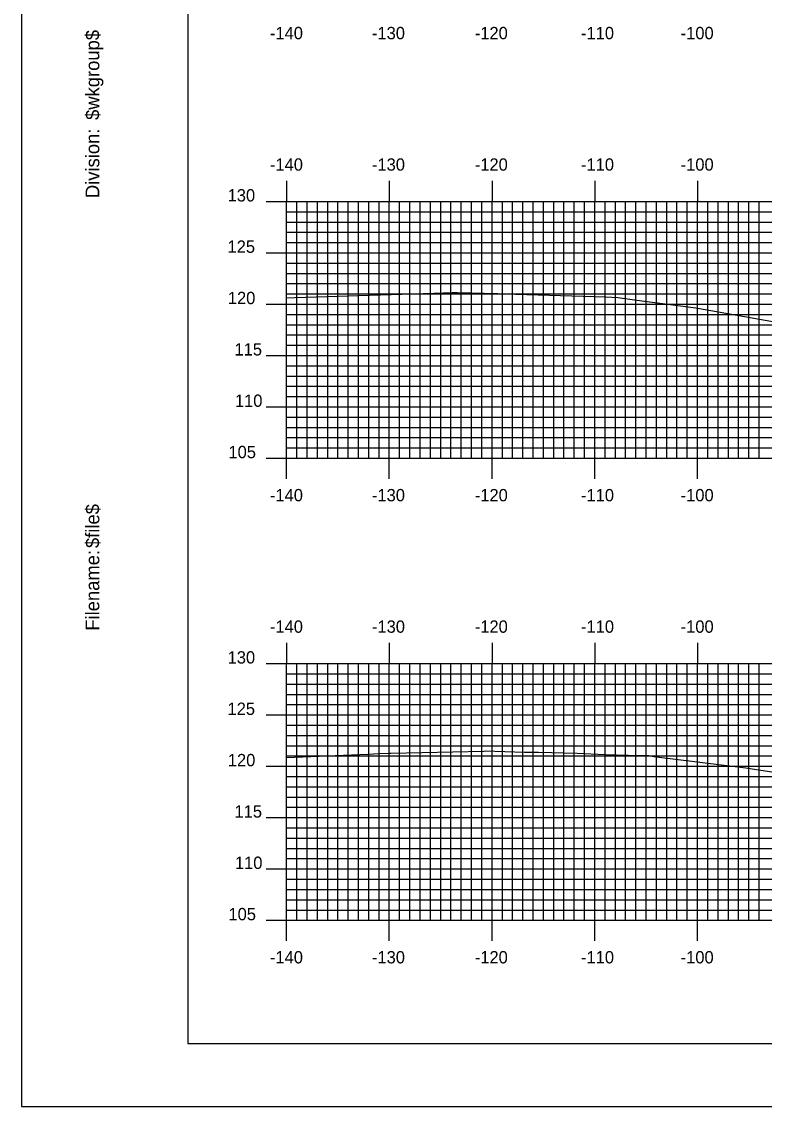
# Model space of a CAD drawing. Extents: x 844143 to 844486, y 363538 to 363758.
# Drawn here: x 844142.7 to 844215, y 363537.6 to 363643.2 of the extents above; entities that cross this region are included whole.
import ezdxf

# ---------------------------------------------------------------- set-up
doc = ezdxf.new("R2010")
doc.units = 0
for name, color, linetype in [('BORDER', 7, 'Continuous'), ('H_V ANNOTATION', 7, 'Continuous'), ('M_Roadway_Centerline', 7, 'Continuous'), ('MAJOR', 7, 'Continuous'), ('MINOR', 7, 'Continuous'), ('PLOT BOUNDARY', 7, 'Continuous'), ('S_Roadway_Centerline', 7, 'Continuous')]:
    doc.layers.add(name, color=color, linetype=linetype)

msp = doc.modelspace()

# ---------------------------------------------------------------- linework, layer by layer
at = {"layer": 'BORDER'}
msp.add_lwpolyline([(844158.85, 363543.72), (844478.85, 363543.72), (844478.85, 363753.72), (844158.85, 363753.72)], close=True, dxfattribs=at)
at = {"layer": 'MAJOR'}
for p, q in [((844168.45, 363627.73), (844168.45, 363625.72)), ((844178.45, 363627.73), (844178.45, 363625.72)), ((844188.45, 363627.73), (844188.45, 363625.72)), ((844198.45, 363627.73), (844198.45, 363625.72)), ((844208.45, 363627.73), (844208.45, 363625.72)), ((844166.45, 363625.72), (844168.45, 363625.72)), ((844168.45, 363625.72), (844448.45, 363625.72)), ((844168.45, 363600.72), (844168.45, 363625.72)), ((844168.45, 363600.72), (844168.45, 363625.72)), ((844168.45, 363625.72), (844448.45, 363625.72)), ((844178.45, 363600.72), (844178.45, 363625.72)), ((844188.45, 363600.72), (844188.45, 363625.72)), ((844198.45, 363600.72), (844198.45, 363625.72)), ((844208.45, 363600.72), (844208.45, 363625.72)), ((844166.45, 363620.72), (844168.45, 363620.72)), ((844168.45, 363620.72), (844448.45, 363620.72)), ((844166.45, 363615.72), (844168.45, 363615.72)), ((844168.45, 363615.72), (844448.45, 363615.72)), ((844166.45, 363610.72), (844168.45, 363610.72)), ((844168.45, 363610.72), (844448.45, 363610.72)), ((844166.45, 363605.72), (844168.45, 363605.72)), ((844168.45, 363605.72), (844448.45, 363605.72)), ((844166.45, 363600.72), (844168.45, 363600.72)), ((844168.45, 363600.72), (844448.45, 363600.72)), ((844168.45, 363600.72), (844448.45, 363600.72)), ((844168.45, 363598.72), (844168.45, 363600.72)), ((844178.45, 363598.72), (844178.45, 363600.72)), ((844188.45, 363598.72), (844188.45, 363600.72)), ((844198.45, 363598.72), (844198.45, 363600.72)), ((844208.45, 363598.72), (844208.45, 363600.72)), ((844168.45, 363582.73), (844168.45, 363580.72)), ((844178.45, 363582.73), (844178.45, 363580.72)), ((844188.45, 363582.73), (844188.45, 363580.72)), ((844198.45, 363582.73), (844198.45, 363580.72)), ((844208.45, 363582.73), (844208.45, 363580.72)), ((844166.45, 363580.72), (844168.45, 363580.72)), ((844168.45, 363580.72), (844448.45, 363580.72)), ((844168.45, 363555.72), (844168.45, 363580.72)), ((844168.45, 363555.72), (844168.45, 363580.72)), ((844168.45, 363580.72), (844448.45, 363580.72)), ((844178.45, 363555.72), (844178.45, 363580.72)), ((844188.45, 363555.72), (844188.45, 363580.72)), ((844198.45, 363555.72), (844198.45, 363580.72)), ((844208.45, 363555.72), (844208.45, 363580.72)), ((844166.45, 363575.72), (844168.45, 363575.72)), ((844168.45, 363575.72), (844448.45, 363575.72)), ((844166.45, 363570.72), (844168.45, 363570.72)), ((844168.45, 363570.72), (844448.45, 363570.72)), ((844166.45, 363565.72), (844168.45, 363565.72)), ((844168.45, 363565.72), (844448.45, 363565.72)), ((844166.45, 363560.72), (844168.45, 363560.72)), ((844168.45, 363560.72), (844448.45, 363560.72)), ((844166.45, 363555.72), (844168.45, 363555.72)), ((844168.45, 363555.72), (844448.45, 363555.72)), ((844168.45, 363555.72), (844448.45, 363555.72)), ((844168.45, 363553.72), (844168.45, 363555.72)), ((844178.45, 363553.72), (844178.45, 363555.72)), ((844188.45, 363553.72), (844188.45, 363555.72)), ((844198.45, 363553.72), (844198.45, 363555.72)), ((844208.45, 363553.72), (844208.45, 363555.72))]:
    msp.add_line(p, q, dxfattribs=at)
at = {"layer": 'MINOR'}
for p, q in [((844169.45, 363600.72), (844169.45, 363625.72)), ((844170.45, 363600.72), (844170.45, 363625.72)), ((844171.45, 363600.72), (844171.45, 363625.72)), ((844172.45, 363600.72), (844172.45, 363625.72)), ((844173.45, 363600.72), (844173.45, 363625.72)), ((844174.45, 363600.72), (844174.45, 363625.72)), ((844175.45, 363600.72), (844175.45, 363625.72)), ((844176.45, 363600.72), (844176.45, 363625.72)), ((844177.45, 363600.72), (844177.45, 363625.72)), ((844179.45, 363600.72), (844179.45, 363625.72)), ((844180.45, 363600.72), (844180.45, 363625.72)), ((844181.45, 363600.72), (844181.45, 363625.72)), ((844182.45, 363600.72), (844182.45, 363625.72)), ((844183.45, 363600.72), (844183.45, 363625.72)), ((844184.45, 363600.72), (844184.45, 363625.72)), ((844185.45, 363600.72), (844185.45, 363625.72)), ((844186.45, 363600.72), (844186.45, 363625.72)), ((844187.45, 363600.72), (844187.45, 363625.72)), ((844189.45, 363600.72), (844189.45, 363625.72)), ((844190.45, 363600.72), (844190.45, 363625.72)), ((844191.45, 363600.72), (844191.45, 363625.72)), ((844192.45, 363600.72), (844192.45, 363625.72)), ((844193.45, 363600.72), (844193.45, 363625.72)), ((844194.45, 363600.72), (844194.45, 363625.72)), ((844195.45, 363600.72), (844195.45, 363625.72)), ((844196.45, 363600.72), (844196.45, 363625.72)), ((844197.45, 363600.72), (844197.45, 363625.72)), ((844199.45, 363600.72), (844199.45, 363625.72)), ((844200.45, 363600.72), (844200.45, 363625.72)), ((844201.45, 363600.72), (844201.45, 363625.72)), ((844202.45, 363600.72), (844202.45, 363625.72)), ((844203.45, 363600.72), (844203.45, 363625.72)), ((844204.45, 363600.72), (844204.45, 363625.72)), ((844205.45, 363600.72), (844205.45, 363625.72)), ((844206.45, 363600.72), (844206.45, 363625.72)), ((844207.45, 363600.72), (844207.45, 363625.72)), ((844209.45, 363600.72), (844209.45, 363625.72)), ((844210.45, 363600.72), (844210.45, 363625.72)), ((844211.45, 363600.72), (844211.45, 363625.72)), ((844212.45, 363600.72), (844212.45, 363625.72)), ((844213.45, 363600.72), (844213.45, 363625.72)), ((844214.45, 363600.72), (844214.45, 363625.72)), ((844168.45, 363624.72), (844448.45, 363624.72)), ((844168.45, 363624.72), (844170.45, 363624.72)), ((844168.45, 363623.72), (844448.45, 363623.72)), ((844168.45, 363623.72), (844170.45, 363623.72)), ((844168.45, 363622.72), (844448.45, 363622.72)), ((844168.45, 363622.72), (844170.45, 363622.72)), ((844168.45, 363621.72), (844448.45, 363621.72)), ((844168.45, 363621.72), (844170.45, 363621.72)), ((844168.45, 363619.72), (844448.45, 363619.72)), ((844168.45, 363619.72), (844170.45, 363619.72)), ((844168.45, 363618.72), (844448.45, 363618.72)), ((844168.45, 363618.72), (844170.45, 363618.72)), ((844168.45, 363617.72), (844448.45, 363617.72)), ((844168.45, 363617.72), (844170.45, 363617.72)), ((844168.45, 363616.72), (844448.45, 363616.72)), ((844168.45, 363616.72), (844170.45, 363616.72)), ((844168.45, 363614.72), (844448.45, 363614.72)), ((844168.45, 363614.72), (844170.45, 363614.72)), ((844168.45, 363613.72), (844448.45, 363613.72)), ((844168.45, 363613.72), (844170.45, 363613.72)), ((844168.45, 363612.72), (844448.45, 363612.72)), ((844168.45, 363612.72), (844170.45, 363612.72)), ((844168.45, 363611.72), (844448.45, 363611.72)), ((844168.45, 363611.72), (844170.45, 363611.72)), ((844168.45, 363609.72), (844448.45, 363609.72)), ((844168.45, 363609.72), (844170.45, 363609.72)), ((844168.45, 363608.72), (844448.45, 363608.72)), ((844168.45, 363608.72), (844170.45, 363608.72)), ((844168.45, 363607.72), (844448.45, 363607.72)), ((844168.45, 363607.72), (844170.45, 363607.72)), ((844168.45, 363606.72), (844448.45, 363606.72)), ((844168.45, 363606.72), (844170.45, 363606.72)), ((844168.45, 363604.72), (844448.45, 363604.72)), ((844168.45, 363604.72), (844170.45, 363604.72)), ((844168.45, 363603.72), (844448.45, 363603.72)), ((844168.45, 363603.72), (844170.45, 363603.72)), ((844168.45, 363602.72), (844448.45, 363602.72)), ((844168.45, 363602.72), (844170.45, 363602.72)), ((844168.45, 363601.72), (844448.45, 363601.72)), ((844168.45, 363601.72), (844170.45, 363601.72)), ((844169.45, 363555.72), (844169.45, 363580.72)), ((844170.45, 363555.72), (844170.45, 363580.72)), ((844171.45, 363555.72), (844171.45, 363580.72)), ((844172.45, 363555.72), (844172.45, 363580.72)), ((844173.45, 363555.72), (844173.45, 363580.72)), ((844174.45, 363555.72), (844174.45, 363580.72)), ((844175.45, 363555.72), (844175.45, 363580.72)), ((844176.45, 363555.72), (844176.45, 363580.72)), ((844177.45, 363555.72), (844177.45, 363580.72)), ((844179.45, 363555.72), (844179.45, 363580.72)), ((844180.45, 363555.72), (844180.45, 363580.72)), ((844181.45, 363555.72), (844181.45, 363580.72)), ((844182.45, 363555.72), (844182.45, 363580.72)), ((844183.45, 363555.72), (844183.45, 363580.72)), ((844184.45, 363555.72), (844184.45, 363580.72)), ((844185.45, 363555.72), (844185.45, 363580.72)), ((844186.45, 363555.72), (844186.45, 363580.72)), ((844187.45, 363555.72), (844187.45, 363580.72)), ((844189.45, 363555.72), (844189.45, 363580.72)), ((844190.45, 363555.72), (844190.45, 363580.72)), ((844191.45, 363555.72), (844191.45, 363580.72)), ((844192.45, 363555.72), (844192.45, 363580.72)), ((844193.45, 363555.72), (844193.45, 363580.72)), ((844194.45, 363555.72), (844194.45, 363580.72)), ((844195.45, 363555.72), (844195.45, 363580.72)), ((844196.45, 363555.72), (844196.45, 363580.72)), ((844197.45, 363555.72), (844197.45, 363580.72)), ((844199.45, 363555.72), (844199.45, 363580.72)), ((844200.45, 363555.72), (844200.45, 363580.72)), ((844201.45, 363555.72), (844201.45, 363580.72)), ((844202.45, 363555.72), (844202.45, 363580.72)), ((844203.45, 363555.72), (844203.45, 363580.72)), ((844204.45, 363555.72), (844204.45, 363580.72)), ((844205.45, 363555.72), (844205.45, 363580.72)), ((844206.45, 363555.72), (844206.45, 363580.72)), ((844207.45, 363555.72), (844207.45, 363580.72)), ((844209.45, 363555.72), (844209.45, 363580.72)), ((844210.45, 363555.72), (844210.45, 363580.72)), ((844211.45, 363555.72), (844211.45, 363580.72)), ((844212.45, 363555.72), (844212.45, 363580.72)), ((844213.45, 363555.72), (844213.45, 363580.72)), ((844214.45, 363555.72), (844214.45, 363580.72)), ((844168.45, 363579.72), (844448.45, 363579.72)), ((844168.45, 363579.72), (844170.45, 363579.72)), ((844168.45, 363578.72), (844448.45, 363578.72)), ((844168.45, 363578.72), (844170.45, 363578.72)), ((844168.45, 363577.72), (844448.45, 363577.72)), ((844168.45, 363577.72), (844170.45, 363577.72)), ((844168.45, 363576.72), (844448.45, 363576.72)), ((844168.45, 363576.72), (844170.45, 363576.72)), ((844168.45, 363574.72), (844448.45, 363574.72)), ((844168.45, 363574.72), (844170.45, 363574.72)), ((844168.45, 363573.72), (844448.45, 363573.72)), ((844168.45, 363573.72), (844170.45, 363573.72)), ((844168.45, 363572.72), (844448.45, 363572.72)), ((844168.45, 363572.72), (844170.45, 363572.72)), ((844168.45, 363571.72), (844448.45, 363571.72)), ((844168.45, 363571.72), (844170.45, 363571.72)), ((844168.45, 363569.72), (844448.45, 363569.72)), ((844168.45, 363569.72), (844170.45, 363569.72)), ((844168.45, 363568.72), (844448.45, 363568.72)), ((844168.45, 363568.72), (844170.45, 363568.72)), ((844168.45, 363567.72), (844448.45, 363567.72)), ((844168.45, 363567.72), (844170.45, 363567.72)), ((844168.45, 363566.72), (844448.45, 363566.72)), ((844168.45, 363566.72), (844170.45, 363566.72)), ((844168.45, 363564.72), (844448.45, 363564.72)), ((844168.45, 363564.72), (844170.45, 363564.72)), ((844168.45, 363563.72), (844448.45, 363563.72)), ((844168.45, 363563.72), (844170.45, 363563.72)), ((844168.45, 363562.72), (844448.45, 363562.72)), ((844168.45, 363562.72), (844170.45, 363562.72)), ((844168.45, 363561.72), (844448.45, 363561.72)), ((844168.45, 363561.72), (844170.45, 363561.72)), ((844168.45, 363559.72), (844448.45, 363559.72)), ((844168.45, 363559.72), (844170.45, 363559.72)), ((844168.45, 363558.72), (844448.45, 363558.72)), ((844168.45, 363558.72), (844170.45, 363558.72)), ((844168.45, 363557.72), (844448.45, 363557.72)), ((844168.45, 363557.72), (844170.45, 363557.72)), ((844168.45, 363556.72), (844448.45, 363556.72)), ((844168.45, 363556.72), (844170.45, 363556.72))]:
    msp.add_line(p, q, dxfattribs=at)
at = {"layer": 'PLOT BOUNDARY'}
msp.add_lwpolyline([(844142.66, 363537.6), (844482.66, 363537.6), (844482.66, 363757.6), (844142.66, 363757.6)], close=True, dxfattribs=at)
at = {"layer": 'S_Roadway_Centerline'}
for points in [[(844168.45, 363616.34), (844169.25, 363616.37), (844182.78, 363616.8), (844184.57, 363616.86), (844184.79, 363616.87), (844184.8, 363616.87), (844184.84, 363616.87), (844185.04, 363616.86), (844189, 363616.75), (844189.62, 363616.72), (844199.54, 363616.44), (844200.69, 363616.37), (844202.54, 363616.1), (844208.3, 363615.37), (844223.61, 363612.64)], [(844168.45, 363571.56), (844176.36, 363571.91), (844177.47, 363571.96), (844178.37, 363572), (844178.6, 363572), (844187.64, 363572.19), (844187.78, 363572.21), (844191.62, 363572.1), (844192.98, 363572.08), (844196.75, 363572), (844199.44, 363571.87), (844202.84, 363571.78), (844203.7, 363571.75), (844204.2, 363571.68), (844213.14, 363570.56), (844217.13, 363569.96)]]:
    msp.add_lwpolyline(points, dxfattribs=at)

# ---------------------------------------------------------------- texts
at = {"layer": 'BORDER'}
for s, p in [('$wkgroup$', (844150.22, 363633.66)), ('Division:', (844150.22, 363626.05)), ('$file$', (844150.22, 363591.97)), ('Filename:', (844150.22, 363583.92))]:
    msp.add_text(s, height=1.339, rotation=90, dxfattribs=at).set_placement(p)
at = {"layer": 'H_V ANNOTATION'}
for s, p in [('-140', (844166.83, 363641.52)), ('-130', (844176.76, 363641.52)), ('-120', (844186.77, 363641.52)), ('-110', (844197.11, 363641.52)), ('-100', (844206.81, 363641.52)), ('-140', (844166.83, 363628.72)), ('-130', (844176.76, 363628.72)), ('-120', (844186.77, 363628.72)), ('-110', (844197.11, 363628.72)), ('-100', (844206.81, 363628.72)), ('130', (844162.71, 363625.72)), ('125', (844162.7, 363620.72)), ('120', (844162.73, 363615.72)), ('115', (844163.38, 363610.72)), ('110', (844163.42, 363605.72)), ('105', (844162.79, 363600.72)), ('-140', (844166.83, 363596.52)), ('-130', (844176.76, 363596.52)), ('-120', (844186.77, 363596.52)), ('-110', (844197.11, 363596.52)), ('-100', (844206.81, 363596.52)), ('-140', (844166.83, 363583.72)), ('-130', (844176.76, 363583.72)), ('-120', (844186.77, 363583.72)), ('-110', (844197.11, 363583.72)), ('-100', (844206.81, 363583.72)), ('130', (844162.71, 363580.72)), ('125', (844162.7, 363575.72)), ('120', (844162.73, 363570.72)), ('115', (844163.38, 363565.72)), ('110', (844163.42, 363560.72)), ('105', (844162.79, 363555.72)), ('-140', (844166.83, 363551.52)), ('-130', (844176.76, 363551.52)), ('-120', (844186.77, 363551.52)), ('-110', (844197.11, 363551.52)), ('-100', (844206.81, 363551.52))]:
    msp.add_text(s, height=1.2, dxfattribs=at).set_placement(p)
at = {"layer": 'M_Roadway_Centerline'}
for s, p in [('C', (844184.79, 363616.87)), ('L', (844184.8, 363616.86)), ('C', (844187.77, 363572.21)), ('L', (844187.78, 363572.21))]:
    msp.add_text(s, height=0.0146, dxfattribs=at).set_placement(p)
at = {"layer": 'MAJOR'}
for p in [(844168.44, 363600.72), (844168.44, 363555.72)]:
    msp.add_text('-', height=0.012, dxfattribs=at).set_placement(p)

doc.saveas('drawing.dxf')
